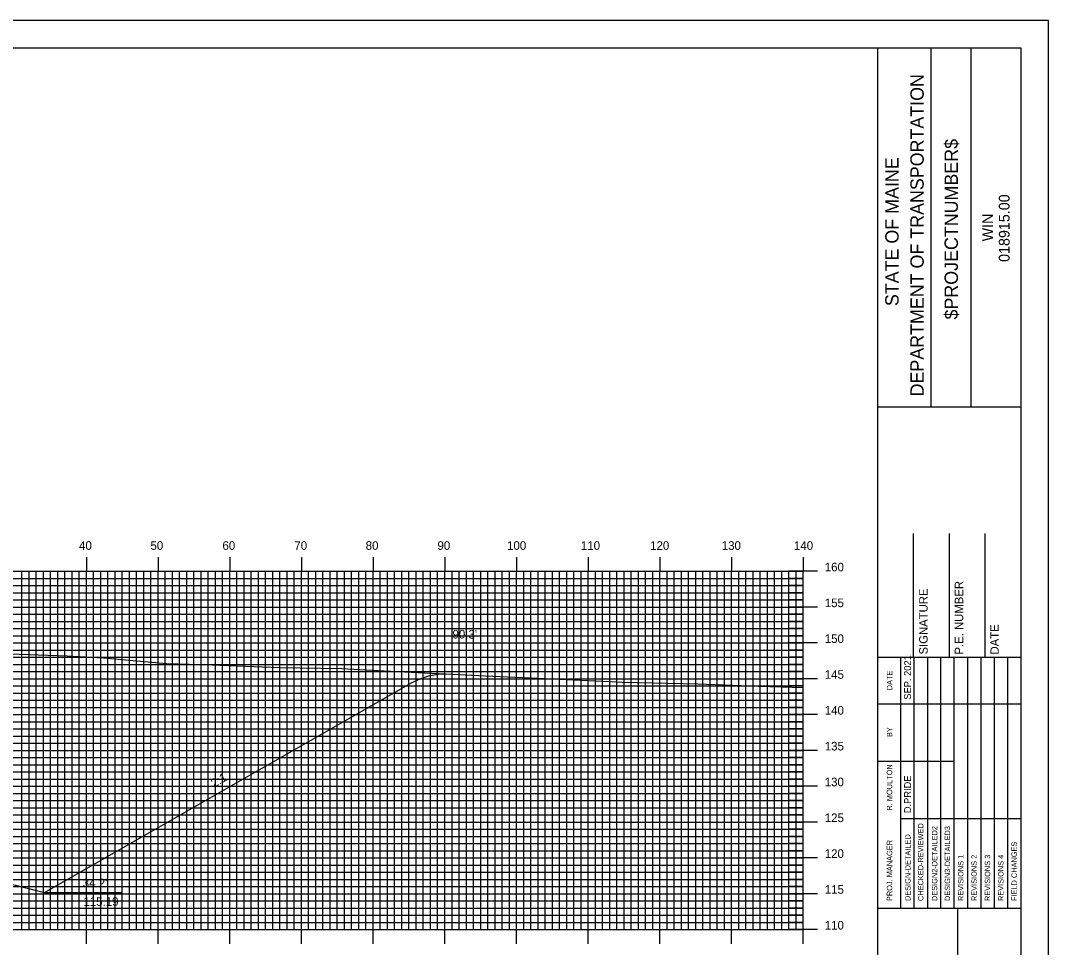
# Model space of a CAD drawing. Extents: x 1770055 to 1770398, y 442591 to 442811.
# Drawn here: x 1770251.3 to 1770394.7, y 442681.2 to 442810.5 of the extents above; entities that cross this region are included whole.
import ezdxf

# ---------------------------------------------------------------- set-up
doc = ezdxf.new("R2010")
doc.units = 0
for name, color, linetype in [('ANNOTATION', 7, 'Continuous'), ('BORDER', 7, 'Continuous'), ('D_Roadway_Centerline', 7, 'Continuous'), ('D_Roadway_SlopeLines', 7, 'Continuous'), ('D_Text_Standard', 7, 'Continuous'), ('H_V ANNOTATION', 7, 'Continuous'), ('MAJOR', 7, 'Continuous'), ('MINOR', 7, 'Continuous'), ('PDRAIN', 7, 'Continuous'), ('PLOT BOUNDARY', 7, 'Continuous'), ('S_Roadway_Centerline', 7, 'Continuous')]:
    doc.layers.add(name, color=color, linetype=linetype)

msp = doc.modelspace()

# ---------------------------------------------------------------- linework, layer by layer
at = {"layer": 'BORDER'}
for p, q in [((1770370.93, 442596.67), (1770370.93, 442806.67)), ((1770378.39, 442756.66), (1770378.39, 442806.66)), ((1770383.98, 442756.66), (1770383.98, 442806.66)), ((1770370.93, 442756.65), (1770390.93, 442756.65)), ((1770375.93, 442721.67), (1770375.93, 442738.97)), ((1770380.93, 442721.67), (1770380.93, 442738.97)), ((1770385.93, 442721.67), (1770385.93, 442738.97)), ((1770370.93, 442721.67), (1770390.93, 442721.67)), ((1770370.93, 442686.67), (1770390.93, 442686.67)), ((1770382.11, 442616.67), (1770382.11, 442686.67))]:
    msp.add_line(p, q, dxfattribs=at)
msp.add_lwpolyline([(1770070.93, 442596.67), (1770390.93, 442596.67), (1770390.93, 442806.67), (1770070.93, 442806.67)], close=True, dxfattribs=at)
for points in [[(1770374.16, 442715.17), (1770374.16, 442721.67)], [(1770376.02, 442686.68), (1770376.02, 442721.67)], [(1770377.89, 442721.67), (1770377.89, 442686.68)], [(1770379.75, 442686.68), (1770379.75, 442721.67)], [(1770381.61, 442686.68), (1770381.61, 442721.67)], [(1770383.48, 442686.68), (1770383.48, 442721.67)], [(1770385.34, 442686.68), (1770385.34, 442721.67)], [(1770387.2, 442686.68), (1770387.2, 442721.67)], [(1770389.07, 442686.68), (1770389.07, 442721.67)], [(1770374.16, 442686.68), (1770374.16, 442720.26)], [(1770370.93, 442715.17), (1770390.93, 442715.17)], [(1770370.93, 442707.17), (1770374.16, 442707.17)], [(1770374.16, 442707.17), (1770381.61, 442707.17)], [(1770374.16, 442699.17), (1770390.93, 442699.17)]]:
    msp.add_lwpolyline(points, dxfattribs=at)
at = {"layer": 'D_Roadway_Centerline'}
msp.add_lwpolyline([(1770250.7, 442689.85), (1770254.14, 442688.99), (1770254.7, 442688.85), (1770305.78, 442718.04), (1770305.79, 442718.04), (1770307.04, 442718.66), (1770308.29, 442719.08), (1770309.54, 442719.31), (1770309.61, 442719.31), (1770310.79, 442719.34)], dxfattribs=at)
at = {"layer": 'D_Roadway_SlopeLines'}
for points in [[(1770254.7, 442688.85), (1770305.79, 442718.04), (1770307.04, 442718.66), (1770308.29, 442719.08), (1770309.54, 442719.31), (1770310.79, 442719.34)], [(1770240.53, 442692.4), (1770254.7, 442688.85)]]:
    msp.add_lwpolyline(points, dxfattribs=at)
at = {"layer": 'MAJOR'}
for p, q in [((1770260.53, 442735.67), (1770260.53, 442733.67)), ((1770270.53, 442735.67), (1770270.53, 442733.67)), ((1770280.53, 442735.67), (1770280.53, 442733.67)), ((1770290.53, 442735.67), (1770290.53, 442733.67)), ((1770300.53, 442735.67), (1770300.53, 442733.67)), ((1770310.53, 442735.67), (1770310.53, 442733.67)), ((1770320.53, 442735.67), (1770320.53, 442733.67)), ((1770330.53, 442735.67), (1770330.53, 442733.67)), ((1770340.53, 442735.67), (1770340.53, 442733.67)), ((1770350.53, 442735.67), (1770350.53, 442733.67)), ((1770360.53, 442735.67), (1770360.53, 442733.67)), ((1770080.53, 442733.67), (1770360.53, 442733.67)), ((1770080.53, 442733.67), (1770360.53, 442733.67)), ((1770260.53, 442683.67), (1770260.53, 442733.67)), ((1770270.53, 442683.67), (1770270.53, 442733.67)), ((1770280.53, 442683.67), (1770280.53, 442733.67)), ((1770290.53, 442683.67), (1770290.53, 442733.67)), ((1770300.53, 442683.67), (1770300.53, 442733.67)), ((1770310.53, 442683.67), (1770310.53, 442733.67)), ((1770320.53, 442683.67), (1770320.53, 442733.67)), ((1770330.53, 442683.67), (1770330.53, 442733.67)), ((1770340.53, 442683.67), (1770340.53, 442733.67)), ((1770350.53, 442683.67), (1770350.53, 442733.67)), ((1770362.53, 442733.67), (1770358.52, 442733.67)), ((1770360.53, 442683.67), (1770360.53, 442733.67)), ((1770360.53, 442683.67), (1770360.53, 442733.67)), ((1770080.53, 442728.67), (1770360.53, 442728.67)), ((1770362.53, 442728.67), (1770358.52, 442728.67)), ((1770080.53, 442723.67), (1770360.53, 442723.67)), ((1770362.53, 442723.67), (1770358.52, 442723.67)), ((1770080.53, 442718.67), (1770360.53, 442718.67)), ((1770362.53, 442718.67), (1770358.52, 442718.67)), ((1770080.53, 442713.67), (1770360.53, 442713.67)), ((1770362.53, 442713.67), (1770358.52, 442713.67)), ((1770080.53, 442708.67), (1770360.53, 442708.67)), ((1770362.53, 442708.67), (1770358.52, 442708.67)), ((1770080.53, 442703.67), (1770360.53, 442703.67)), ((1770362.53, 442703.67), (1770358.52, 442703.67)), ((1770080.53, 442698.67), (1770360.53, 442698.67)), ((1770362.53, 442698.67), (1770358.52, 442698.67)), ((1770080.53, 442693.67), (1770360.53, 442693.67)), ((1770362.53, 442693.67), (1770358.52, 442693.67)), ((1770080.53, 442688.67), (1770360.53, 442688.67)), ((1770362.53, 442688.67), (1770358.52, 442688.67)), ((1770080.53, 442683.67), (1770360.53, 442683.67)), ((1770080.53, 442683.67), (1770360.53, 442683.67)), ((1770260.53, 442681.66), (1770260.53, 442683.67)), ((1770270.53, 442681.66), (1770270.53, 442683.67)), ((1770280.53, 442681.66), (1770280.53, 442683.67)), ((1770290.53, 442681.66), (1770290.53, 442683.67)), ((1770300.53, 442681.66), (1770300.53, 442683.67)), ((1770310.53, 442681.66), (1770310.53, 442683.67)), ((1770320.53, 442681.66), (1770320.53, 442683.67)), ((1770330.53, 442681.66), (1770330.53, 442683.67)), ((1770340.53, 442681.66), (1770340.53, 442683.67)), ((1770350.53, 442681.66), (1770350.53, 442683.67)), ((1770362.53, 442683.67), (1770358.52, 442683.67)), ((1770360.53, 442681.66), (1770360.53, 442683.67))]:
    msp.add_line(p, q, dxfattribs=at)
at = {"layer": 'MINOR'}
for p, q in [((1770080.53, 442732.67), (1770360.53, 442732.67)), ((1770251.53, 442683.67), (1770251.53, 442733.67)), ((1770252.53, 442683.67), (1770252.53, 442733.67)), ((1770253.53, 442683.67), (1770253.53, 442733.67)), ((1770254.53, 442683.67), (1770254.53, 442733.67)), ((1770255.53, 442683.67), (1770255.53, 442733.67)), ((1770256.53, 442683.67), (1770256.53, 442733.67)), ((1770257.53, 442683.67), (1770257.53, 442733.67)), ((1770258.53, 442683.67), (1770258.53, 442733.67)), ((1770259.53, 442683.67), (1770259.53, 442733.67)), ((1770261.53, 442683.67), (1770261.53, 442733.67)), ((1770262.53, 442683.67), (1770262.53, 442733.67)), ((1770263.53, 442683.67), (1770263.53, 442733.67)), ((1770264.53, 442683.67), (1770264.53, 442733.67)), ((1770265.53, 442683.67), (1770265.53, 442733.67)), ((1770266.53, 442683.67), (1770266.53, 442733.67)), ((1770267.53, 442683.67), (1770267.53, 442733.67)), ((1770268.53, 442683.67), (1770268.53, 442733.67)), ((1770269.53, 442683.67), (1770269.53, 442733.67)), ((1770271.53, 442683.67), (1770271.53, 442733.67)), ((1770272.53, 442683.67), (1770272.53, 442733.67)), ((1770273.53, 442683.67), (1770273.53, 442733.67)), ((1770274.53, 442683.67), (1770274.53, 442733.67)), ((1770275.53, 442683.67), (1770275.53, 442733.67)), ((1770276.53, 442683.67), (1770276.53, 442733.67)), ((1770277.53, 442683.67), (1770277.53, 442733.67)), ((1770278.53, 442683.67), (1770278.53, 442733.67)), ((1770279.53, 442683.67), (1770279.53, 442733.67)), ((1770281.53, 442683.67), (1770281.53, 442733.67)), ((1770282.53, 442683.67), (1770282.53, 442733.67)), ((1770283.53, 442683.67), (1770283.53, 442733.67)), ((1770284.53, 442683.67), (1770284.53, 442733.67)), ((1770285.53, 442683.67), (1770285.53, 442733.67)), ((1770286.53, 442683.67), (1770286.53, 442733.67)), ((1770287.53, 442683.67), (1770287.53, 442733.67)), ((1770288.53, 442683.67), (1770288.53, 442733.67)), ((1770289.53, 442683.67), (1770289.53, 442733.67)), ((1770291.53, 442683.67), (1770291.53, 442733.67)), ((1770292.53, 442683.67), (1770292.53, 442733.67)), ((1770293.53, 442683.67), (1770293.53, 442733.67)), ((1770294.53, 442683.67), (1770294.53, 442733.67)), ((1770295.53, 442683.67), (1770295.53, 442733.67)), ((1770296.53, 442683.67), (1770296.53, 442733.67)), ((1770297.53, 442683.67), (1770297.53, 442733.67)), ((1770298.53, 442683.67), (1770298.53, 442733.67)), ((1770299.53, 442683.67), (1770299.53, 442733.67)), ((1770301.53, 442683.67), (1770301.53, 442733.67)), ((1770302.53, 442683.67), (1770302.53, 442733.67)), ((1770303.53, 442683.67), (1770303.53, 442733.67)), ((1770304.53, 442683.67), (1770304.53, 442733.67)), ((1770305.53, 442683.67), (1770305.53, 442733.67)), ((1770306.53, 442683.67), (1770306.53, 442733.67)), ((1770307.53, 442683.67), (1770307.53, 442733.67)), ((1770308.53, 442683.67), (1770308.53, 442733.67)), ((1770309.53, 442683.67), (1770309.53, 442733.67)), ((1770311.53, 442683.67), (1770311.53, 442733.67)), ((1770312.53, 442683.67), (1770312.53, 442733.67)), ((1770313.53, 442683.67), (1770313.53, 442733.67)), ((1770314.53, 442683.67), (1770314.53, 442733.67)), ((1770315.53, 442683.67), (1770315.53, 442733.67)), ((1770316.53, 442683.67), (1770316.53, 442733.67)), ((1770317.53, 442683.67), (1770317.53, 442733.67)), ((1770318.53, 442683.67), (1770318.53, 442733.67)), ((1770319.53, 442683.67), (1770319.53, 442733.67)), ((1770321.53, 442683.67), (1770321.53, 442733.67)), ((1770322.53, 442683.67), (1770322.53, 442733.67)), ((1770323.53, 442683.67), (1770323.53, 442733.67)), ((1770324.53, 442683.67), (1770324.53, 442733.67)), ((1770325.53, 442683.67), (1770325.53, 442733.67)), ((1770326.53, 442683.67), (1770326.53, 442733.67)), ((1770327.53, 442683.67), (1770327.53, 442733.67)), ((1770328.53, 442683.67), (1770328.53, 442733.67)), ((1770329.53, 442683.67), (1770329.53, 442733.67)), ((1770331.53, 442683.67), (1770331.53, 442733.67)), ((1770332.53, 442683.67), (1770332.53, 442733.67)), ((1770333.53, 442683.67), (1770333.53, 442733.67)), ((1770334.53, 442683.67), (1770334.53, 442733.67)), ((1770335.53, 442683.67), (1770335.53, 442733.67)), ((1770336.53, 442683.67), (1770336.53, 442733.67)), ((1770337.53, 442683.67), (1770337.53, 442733.67)), ((1770338.53, 442683.67), (1770338.53, 442733.67)), ((1770339.53, 442683.67), (1770339.53, 442733.67)), ((1770341.53, 442683.67), (1770341.53, 442733.67)), ((1770342.53, 442683.67), (1770342.53, 442733.67)), ((1770343.53, 442683.67), (1770343.53, 442733.67)), ((1770344.53, 442683.67), (1770344.53, 442733.67)), ((1770345.53, 442683.67), (1770345.53, 442733.67)), ((1770346.53, 442683.67), (1770346.53, 442733.67)), ((1770347.53, 442683.67), (1770347.53, 442733.67)), ((1770348.53, 442683.67), (1770348.53, 442733.67)), ((1770349.53, 442683.67), (1770349.53, 442733.67)), ((1770351.53, 442683.67), (1770351.53, 442733.67)), ((1770352.53, 442683.67), (1770352.53, 442733.67)), ((1770353.53, 442683.67), (1770353.53, 442733.67)), ((1770354.53, 442683.67), (1770354.53, 442733.67)), ((1770355.53, 442683.67), (1770355.53, 442733.67)), ((1770356.53, 442683.67), (1770356.53, 442733.67)), ((1770357.53, 442683.67), (1770357.53, 442733.67)), ((1770360.53, 442732.67), (1770358.52, 442732.67)), ((1770358.53, 442683.67), (1770358.53, 442733.67)), ((1770359.53, 442683.67), (1770359.53, 442733.67)), ((1770080.53, 442731.67), (1770360.53, 442731.67)), ((1770360.53, 442731.67), (1770358.52, 442731.67)), ((1770080.53, 442730.67), (1770360.53, 442730.67)), ((1770360.53, 442730.67), (1770358.52, 442730.67)), ((1770080.53, 442729.67), (1770360.53, 442729.67)), ((1770360.53, 442729.67), (1770358.52, 442729.67)), ((1770080.53, 442727.67), (1770360.53, 442727.67)), ((1770360.53, 442727.67), (1770358.52, 442727.67)), ((1770080.53, 442726.67), (1770360.53, 442726.67)), ((1770080.53, 442725.67), (1770360.53, 442725.67)), ((1770360.53, 442726.67), (1770358.52, 442726.67)), ((1770360.53, 442725.67), (1770358.52, 442725.67)), ((1770080.53, 442724.67), (1770360.53, 442724.67)), ((1770360.53, 442724.67), (1770358.52, 442724.67)), ((1770080.53, 442722.67), (1770360.53, 442722.67)), ((1770360.53, 442722.67), (1770358.52, 442722.67)), ((1770080.53, 442721.67), (1770360.53, 442721.67)), ((1770360.53, 442721.67), (1770358.52, 442721.67)), ((1770080.53, 442720.67), (1770360.53, 442720.67)), ((1770080.53, 442719.67), (1770360.53, 442719.67)), ((1770360.53, 442720.67), (1770358.52, 442720.67)), ((1770360.53, 442719.67), (1770358.52, 442719.67)), ((1770080.53, 442717.67), (1770360.53, 442717.67)), ((1770360.53, 442717.67), (1770358.52, 442717.67)), ((1770080.53, 442716.67), (1770360.53, 442716.67)), ((1770080.53, 442715.67), (1770360.53, 442715.67)), ((1770360.53, 442716.67), (1770358.52, 442716.67)), ((1770360.53, 442715.67), (1770358.52, 442715.67)), ((1770080.53, 442714.67), (1770360.53, 442714.67)), ((1770360.53, 442714.67), (1770358.52, 442714.67)), ((1770080.53, 442712.67), (1770360.53, 442712.67)), ((1770360.53, 442712.67), (1770358.52, 442712.67)), ((1770080.53, 442711.67), (1770360.53, 442711.67)), ((1770360.53, 442711.67), (1770358.52, 442711.67)), ((1770080.53, 442710.67), (1770360.53, 442710.67)), ((1770080.53, 442709.67), (1770360.53, 442709.67)), ((1770360.53, 442710.67), (1770358.52, 442710.67)), ((1770360.53, 442709.67), (1770358.52, 442709.67)), ((1770080.53, 442707.67), (1770360.53, 442707.67)), ((1770360.53, 442707.67), (1770358.52, 442707.67)), ((1770080.53, 442706.67), (1770360.53, 442706.67)), ((1770080.53, 442705.67), (1770360.53, 442705.67)), ((1770360.53, 442706.67), (1770358.52, 442706.67)), ((1770360.53, 442705.67), (1770358.52, 442705.67)), ((1770080.53, 442704.67), (1770360.53, 442704.67)), ((1770360.53, 442704.67), (1770358.52, 442704.67)), ((1770080.53, 442702.67), (1770360.53, 442702.67)), ((1770360.53, 442702.67), (1770358.52, 442702.67)), ((1770080.53, 442701.67), (1770360.53, 442701.67)), ((1770360.53, 442701.67), (1770358.52, 442701.67)), ((1770080.53, 442700.67), (1770360.53, 442700.67)), ((1770080.53, 442699.67), (1770360.53, 442699.67)), ((1770360.53, 442700.67), (1770358.52, 442700.67)), ((1770360.53, 442699.67), (1770358.52, 442699.67)), ((1770080.53, 442697.67), (1770360.53, 442697.67)), ((1770360.53, 442697.67), (1770358.52, 442697.67)), ((1770080.53, 442696.67), (1770360.53, 442696.67)), ((1770080.53, 442695.67), (1770360.53, 442695.67)), ((1770360.53, 442696.67), (1770358.52, 442696.67)), ((1770360.53, 442695.67), (1770358.52, 442695.67)), ((1770080.53, 442694.67), (1770360.53, 442694.67)), ((1770360.53, 442694.67), (1770358.52, 442694.67)), ((1770080.53, 442692.67), (1770360.53, 442692.67)), ((1770360.53, 442692.67), (1770358.52, 442692.67)), ((1770080.53, 442691.67), (1770360.53, 442691.67)), ((1770360.53, 442691.67), (1770358.52, 442691.67)), ((1770080.53, 442690.67), (1770360.53, 442690.67)), ((1770080.53, 442689.67), (1770360.53, 442689.67)), ((1770360.53, 442690.67), (1770358.52, 442690.67)), ((1770360.53, 442689.67), (1770358.52, 442689.67)), ((1770080.53, 442687.67), (1770360.53, 442687.67)), ((1770360.53, 442687.67), (1770358.52, 442687.67)), ((1770080.53, 442686.67), (1770360.53, 442686.67)), ((1770080.53, 442685.67), (1770360.53, 442685.67)), ((1770360.53, 442686.67), (1770358.52, 442686.67)), ((1770360.53, 442685.67), (1770358.52, 442685.67)), ((1770080.53, 442684.67), (1770360.53, 442684.67)), ((1770360.53, 442684.67), (1770358.52, 442684.67))]:
    msp.add_line(p, q, dxfattribs=at)
at = {"layer": 'PDRAIN'}
msp.add_line((1770254.7, 442688.85), (1770265.47, 442688.85), dxfattribs=at)
at = {"layer": 'PLOT BOUNDARY'}
msp.add_lwpolyline([(1770054.74, 442590.55), (1770394.74, 442590.55), (1770394.74, 442810.55), (1770054.74, 442810.55)], close=True, dxfattribs=at)
at = {"layer": 'S_Roadway_Centerline'}
msp.add_lwpolyline([(1770240.34, 442722.48), (1770257.86, 442721.88), (1770262.91, 442721.61), (1770271.7, 442720.8), (1770278.03, 442720.6), (1770287.46, 442720.23), (1770296.18, 442720.11), (1770302.07, 442719.79), (1770316.19, 442719.07), (1770332.55, 442718.34), (1770334.37, 442718.24), (1770335.26, 442718.22), (1770345.83, 442717.99), (1770354.3, 442717.62), (1770360.53, 442717.44)], dxfattribs=at)

# ---------------------------------------------------------------- texts
at = {"layer": 'ANNOTATION'}
msp.add_text('2:1', height=1.2, rotation=29.7444, dxfattribs=at).set_placement((1770278.32, 442703.45))
for s, p in [("34.2'", (1770260.01, 442689.58)), ('115.19', (1770260.1, 442686.98))]:
    msp.add_text(s, height=1.2, dxfattribs=at).set_placement(p)
at = {"layer": 'BORDER'}
for s, height, p in [('DEPARTMENT OF TRANSPORTATION', 1.8635, (1770377.34, 442758.08)), ('$PROJECTNUMBER$', 1.8635, (1770382.11, 442768.82)), ('STATE OF MAINE', 1.8635, (1770373.84, 442770.69)), ('018915.00', 1.491, (1770389.32, 442776.86)), ('WIN', 1.491, (1770387, 442779.73)), ('SIGNATURE', 1.181, (1770377.89, 442722.06)), ('P.E. NUMBER', 1.1811, (1770382.85, 442722.06)), ('DATE', 1.181, (1770387.81, 442722.06)), ('SEP. 2021', 0.969, (1770375.57, 442715.76)), ('DATE', 0.743, (1770372.94, 442717.08)), ('BY', 0.743, (1770372.94, 442710.54)), ('R. MOULTON', 0.745, (1770372.94, 442700.28)), ('D.PRIDE', 0.969, (1770375.57, 442699.92)), ('CHECKED-REVIEWED', 0.7455, (1770377.29, 442687.65)), ('DESIGN2-DETAILED2', 0.7455, (1770379.23, 442687.65)), ('DESIGN3-DETAILED3', 0.7455, (1770381.02, 442687.65)), ('PROJ. MANAGER', 0.7455, (1770372.94, 442687.65)), ('DESIGN-DETAILED', 0.7455, (1770375.5, 442687.65)), ('FIELD CHANGES', 0.7455, (1770390.33, 442687.65)), ('REVISIONS 1', 0.7455, (1770382.88, 442687.65)), ('REVISIONS 2', 0.7455, (1770384.74, 442687.65)), ('REVISIONS 3', 0.7455, (1770386.61, 442687.65)), ('REVISIONS 4', 0.7455, (1770388.47, 442687.65))]:
    msp.add_text(s, height=height, rotation=90, dxfattribs=at).set_placement(p)
at = {"layer": 'D_Text_Standard'}
msp.add_text("90.3'", height=1.2, dxfattribs=at).set_placement((1770311.6, 442724.29))
at = {"layer": 'H_V ANNOTATION'}
for s, p in [('40', (1770259.5, 442736.67)), ('50', (1770269.46, 442736.67)), ('60', (1770279.5, 442736.67)), ('70', (1770289.53, 442736.67)), ('80', (1770299.48, 442736.67)), ('90', (1770309.5, 442736.67)), ('100', (1770319.21, 442736.67)), ('110', (1770329.51, 442736.67)), ('120', (1770339.17, 442736.67)), ('130', (1770349.16, 442736.67)), ('140', (1770359.23, 442736.67)), ('160', (1770363.53, 442733.67)), ('155', (1770363.53, 442728.67)), ('150', (1770363.53, 442723.67)), ('145', (1770363.53, 442718.67)), ('140', (1770363.53, 442713.67)), ('135', (1770363.53, 442708.67)), ('130', (1770363.53, 442703.67)), ('125', (1770363.53, 442698.67)), ('120', (1770363.53, 442693.67)), ('115', (1770363.53, 442688.67)), ('110', (1770363.53, 442683.67))]:
    msp.add_text(s, height=1.2, dxfattribs=at).set_placement(p)

doc.saveas('drawing.dxf')
